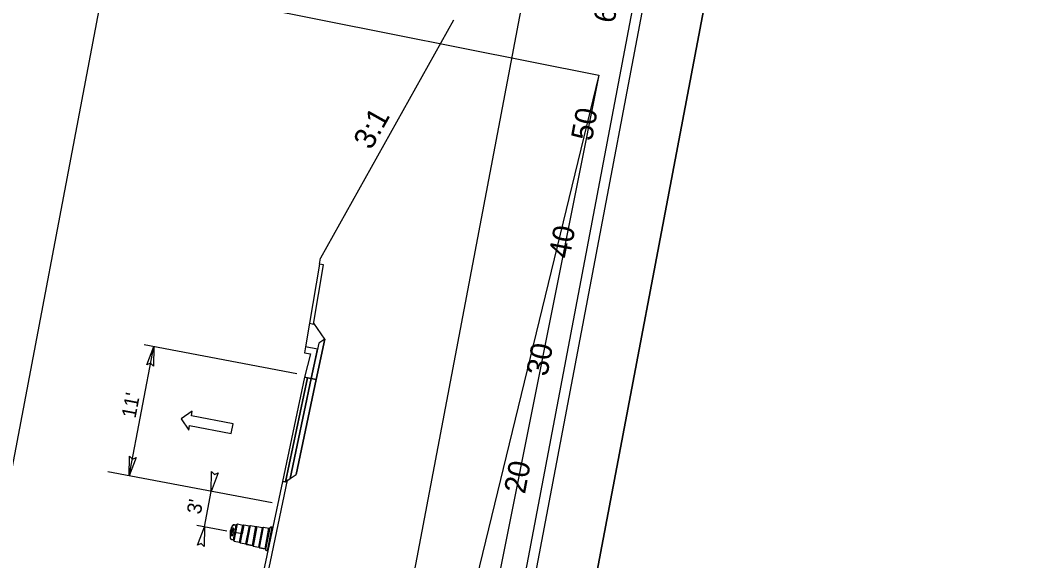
# Model space of a CAD drawing. Extents: x 1615680 to 1617075, y 898420 to 901168.
# Drawn here: x 1616656.3 to 1617075.3, y 900030.6 to 900256.5 of the extents above; entities that cross this region are included whole.
import ezdxf

# ---------------------------------------------------------------- set-up
doc = ezdxf.new("R2010")
doc.units = 0
for name, color, linetype in [('Default', 7, 'Continuous'), ('DEV BORDER CELL', 7, 'Continuous'), ('DEV DRUM SECTIONAL VIEW CELL', 7, 'Continuous'), ('North Arrow', 7, 'Continuous'), ('Old_Level_11', 7, 'Continuous'), ('Prop CMT Pvmt Course 1', 7, 'Continuous'), ('Prop CMT Pvmt Course 2', 7, 'Continuous'), ('Prop CMT Pvmt Course 3', 7, 'Continuous'), ('Prop CMT Subgrade Earthwork', 7, 'Continuous'), ('Prop Conc 4in Sidewalk', 7, 'Continuous'), ('Prop Conc Curb and Gutter', 7, 'Continuous'), ('Prop Corridor Mesh Bottom', 7, 'Continuous'), ('Prop Dimension Text', 7, 'Continuous'), ('Prop XS Finish Grade', 7, 'Continuous'), ('Prop XS Label Text', 7, 'Continuous'), ('Prop XS Offset Labels', 7, 'Continuous'), ('Scratch_Level_0', 7, 'Continuous'), ('Scratch_Level_9', 7, 'Continuous'), ('Sheet Clip Boundary CELL', 7, 'Continuous'), ('Sheet Cross Section CELL', 7, 'Continuous'), ('Sheet Plot Border Outside CELL', 7, 'Continuous')]:
    doc.layers.add(name, color=color, linetype=linetype)

msp = doc.modelspace()

# ---------------------------------------------------------------- linework, layer by layer
at = {"layer": 'Default'}
for points in [[(1616709.31, 900112.48), (1616712.19, 900120.18), (1616712.09, 900111.91), (1616710.87, 900113.19)], [(1616704.81, 900073.84), (1616701.93, 900066.14), (1616702.04, 900074.41), (1616703.26, 900073.13)], [(1616739.07, 900067.34), (1616736.19, 900059.64), (1616736.29, 900067.91), (1616737.51, 900066.62)], [(1616730.51, 900037.2), (1616733.39, 900044.9), (1616733.28, 900036.63), (1616732.06, 900037.92)]]:
    msp.add_lwpolyline(points, close=True, dxfattribs=at)
at = {"layer": 'DEV BORDER CELL'}
msp.add_lwpolyline([(1616014.55, 901139.21), (1615734.74, 899665.53), (1616766.32, 899469.67), (1617046.12, 900943.35)], close=True, dxfattribs=at)
at = {"layer": 'DEV DRUM SECTIONAL VIEW CELL'}
for p, q in [((1616745.47, 900039.42), (1616746.64, 900045.57)), ((1616745.76, 900038.82), (1616747.13, 900046.02)), ((1616746.64, 900045.57), (1616745.92, 900045.71)), ((1616747.13, 900046.02), (1616749.44, 900045.58)), ((1616748.07, 900038.38), (1616749.44, 900045.58)), ((1616748.42, 900038.14), (1616749.85, 900045.69)), ((1616749.44, 900045.58), (1616749.85, 900045.69)), ((1616749.85, 900045.69), (1616752.16, 900045.25)), ((1616750.73, 900037.7), (1616752.16, 900045.25)), ((1616751.08, 900037.45), (1616752.58, 900045.35)), ((1616752.16, 900045.25), (1616752.58, 900045.35)), ((1616752.58, 900045.35), (1616754.89, 900044.91)), ((1616744.82, 900041.14), (1616744.78, 900041.14)), ((1616745.4, 900044.21), (1616745.37, 900044.22)), ((1616753.39, 900037.01), (1616754.89, 900044.91)), ((1616753.74, 900036.76), (1616755.31, 900045.01)), ((1616754.89, 900044.91), (1616755.31, 900045.01)), ((1616755.31, 900045.01), (1616757.62, 900044.57)), ((1616756.05, 900036.33), (1616757.62, 900044.57)), ((1616756.4, 900036.08), (1616758.03, 900044.67)), ((1616757.62, 900044.57), (1616758.03, 900044.67)), ((1616758.03, 900044.67), (1616760.34, 900044.24)), ((1616758.71, 900035.64), (1616760.34, 900044.24)), ((1616759.05, 900035.34), (1616760.77, 900044.39)), ((1616759.75, 900034.81), (1616761.61, 900044.63)), ((1616760.34, 900044.24), (1616760.76, 900044.34)), ((1616761.61, 900044.63), (1616761.23, 900044.7)), ((1616745.47, 900039.42), (1616744.75, 900039.55)), ((1616745.76, 900038.82), (1616748.07, 900038.38)), ((1616748.07, 900038.38), (1616748.42, 900038.14)), ((1616748.42, 900038.14), (1616750.73, 900037.7)), ((1616750.73, 900037.7), (1616751.08, 900037.45)), ((1616751.08, 900037.45), (1616753.39, 900037.01)), ((1616753.39, 900037.01), (1616753.74, 900036.76)), ((1616753.74, 900036.76), (1616756.05, 900036.33)), ((1616756.05, 900036.33), (1616756.4, 900036.08)), ((1616756.4, 900036.08), (1616758.71, 900035.64)), ((1616758.71, 900035.64), (1616759.06, 900035.39)), ((1616759.75, 900034.81), (1616759.37, 900034.88))]:
    msp.add_line(p, q, dxfattribs=at)
for points in [[(1616749.85, 900045.69), (1616749.14, 900041.91), (1616745.29, 900042.64), (1616745.35, 900042.96), (1616745.41, 900043.18), (1616745.46, 900043.38), (1616745.51, 900043.54), (1616745.56, 900043.71), (1616745.61, 900043.86), (1616745.63, 900043.93), (1616745.63, 900043.99), (1616745.6, 900044.07), (1616745.55, 900044.13), (1616745.5, 900044.18), (1616745.44, 900044.21), (1616745.37, 900044.22), (1616745.28, 900044.23), (1616745.2, 900044.2), (1616745.15, 900044.17), (1616745.11, 900044.12), (1616745.08, 900044.09), (1616745.06, 900044.04), (1616745.02, 900043.92), (1616744.98, 900043.79), (1616744.94, 900043.66), (1616744.89, 900043.53), (1616744.85, 900043.36), (1616744.8, 900043.17), (1616744.77, 900043.03), (1616744.74, 900042.9), (1616744.71, 900042.75), (1616744.23, 900042.84), (1616744.27, 900043.07), (1616744.31, 900043.24), (1616744.37, 900043.49), (1616744.42, 900043.65), (1616744.47, 900043.84), (1616744.54, 900044.04), (1616744.63, 900044.28), (1616744.72, 900044.52), (1616744.83, 900044.79), (1616744.94, 900045.02), (1616745.03, 900045.22), (1616745.08, 900045.3), (1616745.13, 900045.39), (1616745.2, 900045.47), (1616745.27, 900045.55), (1616745.35, 900045.59), (1616745.44, 900045.65), (1616745.53, 900045.68), (1616745.63, 900045.71), (1616745.71, 900045.72), (1616745.81, 900045.73), (1616745.89, 900045.72), (1616745.92, 900045.71), (1616746.64, 900045.57), (1616746.74, 900045.7), (1616746.79, 900045.77), (1616746.86, 900045.83), (1616746.93, 900045.9), (1616747.03, 900045.97), (1616747.09, 900046), (1616747.13, 900046.02), (1616749.44, 900045.58)], [(1616750.73, 900037.7), (1616752.16, 900045.25), (1616752.58, 900045.35), (1616754.89, 900044.91), (1616755.31, 900045.01), (1616753.74, 900036.76), (1616753.39, 900037.01), (1616751.08, 900037.45)], [(1616748.42, 900038.14), (1616749.14, 900041.91), (1616745.29, 900042.64), (1616745.25, 900042.45), (1616745.23, 900042.31), (1616745.21, 900042.16), (1616745.19, 900042.01), (1616745.17, 900041.84), (1616745.16, 900041.66), (1616745.15, 900041.47), (1616745.14, 900041.35), (1616745.12, 900041.28), (1616745.08, 900041.23), (1616745.02, 900041.18), (1616744.97, 900041.15), (1616744.91, 900041.13), (1616744.86, 900041.13), (1616744.75, 900041.15), (1616744.7, 900041.18), (1616744.64, 900041.22), (1616744.6, 900041.28), (1616744.57, 900041.36), (1616744.56, 900041.42), (1616744.57, 900041.56), (1616744.58, 900041.76), (1616744.62, 900042.15), (1616744.66, 900042.43), (1616744.69, 900042.64), (1616744.71, 900042.75), (1616744.23, 900042.84), (1616744.19, 900042.64), (1616744.15, 900042.38), (1616744.12, 900042.11), (1616744.09, 900041.83), (1616744.08, 900041.56), (1616744.07, 900041.26), (1616744.07, 900040.91), (1616744.08, 900040.71), (1616744.11, 900040.38), (1616744.12, 900040.24), (1616744.14, 900040.15), (1616744.17, 900040.05), (1616744.21, 900039.95), (1616744.29, 900039.83), (1616744.37, 900039.75), (1616744.44, 900039.69), (1616744.53, 900039.63), (1616744.63, 900039.59), (1616744.75, 900039.55), (1616745.47, 900039.42), (1616745.49, 900039.34), (1616745.51, 900039.26), (1616745.55, 900039.16), (1616745.61, 900039.05), (1616745.66, 900038.96), (1616745.76, 900038.82), (1616748.07, 900038.38)], [(1616756.05, 900036.33), (1616757.62, 900044.57), (1616758.03, 900044.67), (1616760.34, 900044.24), (1616760.76, 900044.34), (1616760.78, 900044.43), (1616760.81, 900044.49), (1616760.85, 900044.56), (1616760.9, 900044.62), (1616760.95, 900044.65), (1616761.01, 900044.68), (1616761.09, 900044.7), (1616761.14, 900044.71), (1616761.19, 900044.71), (1616761.23, 900044.7), (1616761.61, 900044.63), (1616759.75, 900034.81), (1616759.37, 900034.88), (1616759.31, 900034.9), (1616759.25, 900034.92), (1616759.2, 900034.96), (1616759.16, 900035), (1616759.13, 900035.03), (1616759.09, 900035.1), (1616759.06, 900035.16), (1616759.05, 900035.24), (1616759.05, 900035.28), (1616759.05, 900035.34), (1616759.06, 900035.39), (1616758.71, 900035.64), (1616756.4, 900036.08)]]:
    msp.add_lwpolyline(points, close=True, dxfattribs=at)
for centre, radius, start, end in [((1616752.92, 900041.19), 8.85, 152.3001, 186.1986), ((1616745.78, 900044.94), 0.783, 79.2494, 152.3001), ((1616747.78, 900044.84), 1.35, 118.7358, 146.9434), ((1616753.4, 900041.1), 8.85, 160.5754, 177.9234), ((1616744.84, 900041.41), 0.274, 177.9234, 259.2494), ((1616744.87, 900041.41), 0.274, 259.2494, 357.3981), ((1616745.32, 900043.95), 0.274, 79.2494, 160.5754), ((1616753.98, 900040.99), 8.85, 161.1006, 177.3981), ((1616745.35, 900043.95), 0.274, 341.1006, 79.2494), ((1616761.16, 900044.31), 0.392, 79.2494, 169.2494), ((1616744.9, 900040.32), 0.783, 186.1986, 259.2494), ((1616746.8, 900039.69), 1.35, 191.5554, 219.7629), ((1616759.44, 900035.27), 0.392, 169.2494, 259.2494)]:
    msp.add_arc(centre, radius, start, end, dxfattribs=at)
at = {"layer": 'North Arrow'}
msp.add_line((1616761.71, 900054.79), (1616693, 900067.84), dxfattribs=at)
at = {"layer": 'Old_Level_11'}
for p, q in [((1616708.25, 900120.92), (1616772.02, 900108.82)), ((1616701.93, 900066.14), (1616712.19, 900120.18)), ((1616733.39, 900044.9), (1616736.19, 900059.64)), ((1616730.22, 900045.5), (1616742.71, 900043.13))]:
    msp.add_line(p, q, dxfattribs=at)
at = {"layer": 'Prop CMT Pvmt Course 1'}
for p, q in [((1616765.99, 900063.81), (1616749.65, 899986.23)), ((1616767.12, 900063.6), (1616765.99, 900063.81)), ((1616765.99, 900063.81), (1616765.99, 900063.81))]:
    msp.add_line(p, q, dxfattribs=at)
msp.add_lwpolyline([(1616765.99, 900063.81), (1616765.99, 900063.81), (1616765.99, 900063.81), (1616767.22, 900063.58), (1616767.22, 900063.58), (1616776.39, 900107.11), (1616775.17, 900107.35), (1616775.17, 900107.35), (1616765.99, 900063.81)], dxfattribs=at)
at = {"layer": 'Prop CMT Pvmt Course 2'}
msp.add_lwpolyline([(1616767.24, 900063.68), (1616767.24, 900063.68), (1616767.24, 900063.68), (1616769.23, 900065.04), (1616769.23, 900065.04), (1616778.03, 900106.8), (1616776.39, 900107.11), (1616776.39, 900107.11), (1616767.24, 900063.68)], dxfattribs=at)
at = {"layer": 'Prop CMT Pvmt Course 3'}
for p, q in [((1616751.59, 899985.86), (1616768.11, 900064.28)), ((1616768.11, 900064.28), (1616767.12, 900063.6)), ((1616767.12, 900063.6), (1616767.12, 900063.6))]:
    msp.add_line(p, q, dxfattribs=at)
for points in [[(1616778.03, 900106.8), (1616780.08, 900106.41), (1616783.61, 900123.18), (1616781.12, 900121.49), (1616778.03, 900106.8)], [(1616769.23, 900065.04), (1616769.23, 900065.04), (1616769.23, 900065.04), (1616771.72, 900066.73), (1616771.72, 900066.73), (1616780.08, 900106.41), (1616778.03, 900106.8), (1616778.03, 900106.8), (1616769.23, 900065.04)]]:
    msp.add_lwpolyline(points, dxfattribs=at)
at = {"layer": 'Prop CMT Subgrade Earthwork'}
for points in [[(1616783.61, 900123.18), (1616779.01, 900129.94)], [(1616783.61, 900123.18), (1616780.08, 900106.41), (1616780.08, 900106.41)], [(1616780.08, 900106.41), (1616771.72, 900066.73), (1616771.72, 900066.73)]]:
    msp.add_lwpolyline(points, dxfattribs=at)
at = {"layer": 'Prop Conc 4in Sidewalk'}
msp.add_lwpolyline([(1616777.3, 900129.85), (1616778.93, 900129.49), (1616783.12, 900154.24), (1616781.47, 900154.5), (1616777.3, 900129.85)], dxfattribs=at)
at = {"layer": 'Prop Conc Curb and Gutter'}
msp.add_lwpolyline([(1616775.17, 900107.35), (1616775.17, 900107.35), (1616775.17, 900107.35), (1616778.03, 900106.8), (1616778.03, 900106.8), (1616780.61, 900119.04), (1616775.63, 900119.99), (1616775.63, 900119.99), (1616775.17, 900117.53), (1616775.17, 900117.53), (1616775.17, 900117.53), (1616777.62, 900117.06), (1616775.17, 900107.35)], dxfattribs=at)
at = {"layer": 'Prop Corridor Mesh Bottom'}
msp.add_lwpolyline([(1616775.17, 900107.35), (1616776.39, 900107.11)], dxfattribs=at)
at = {"layer": 'Prop Dimension Text'}
for p, q in [((1616728.29, 900093.08), (1616723.64, 900089.97)), ((1616727.94, 900091.22), (1616728.29, 900093.08)), ((1616723.64, 900089.97), (1616726.8, 900085.25)), ((1616745.34, 900087.91), (1616727.94, 900091.22)), ((1616744.56, 900083.81), (1616745.34, 900087.91)), ((1616726.8, 900085.25), (1616727.16, 900087.11)), ((1616727.16, 900087.11), (1616744.56, 900083.81))]:
    msp.add_line(p, q, dxfattribs=at)
at = {"layer": 'Prop XS Finish Grade'}
for points in [[(1616837.46, 900256.47), (1616781.89, 900156.97), (1616781.89, 900156.97)], [(1616781.47, 900154.5), (1616781.89, 900156.97)], [(1616777.3, 900129.85), (1616777.3, 900129.85), (1616775.63, 900119.99)]]:
    msp.add_lwpolyline(points, dxfattribs=at)
at = {"layer": 'Scratch_Level_0'}
msp.add_lwpolyline([(1616054.34, 901080.76), (1615793.19, 899705.33), (1616726.52, 899528.12), (1616890.46, 900391.55), (1616774.26, 900413.61), (1616871.48, 900925.61)], close=True, dxfattribs=at)
at = {"layer": 'Sheet Clip Boundary CELL'}
for points in [[(1616176.29, 901060.7), (1616848.46, 900914.27), (1616896.28, 900812.91), (1616872.94, 900688.21), (1616835.87, 900695.21), (1616753.94, 900262.18), (1616898.09, 900233.43), (1616734.79, 899562.1), (1616202.98, 899609.43), (1616198.71, 899647.14), (1615822.69, 899825.07), (1616054.34, 901080.76)], [(1616176.29, 901060.7), (1616914, 900899.99), (1616896.28, 900812.91), (1616872.94, 900688.21), (1616835.87, 900695.21), (1616753.94, 900262.18), (1616898.09, 900233.43), (1616747.89, 899480.25), (1615915.8, 899646.19), (1615751.76, 899738.03), (1615981.58, 900932.46), (1616145.94, 900899.57)]]:
    msp.add_lwpolyline(points, close=True, dxfattribs=at)
at = {"layer": 'Sheet Cross Section CELL'}
for p, q in [((1616723.15, 900439.56), (1616559.31, 899576.61)), ((1616774.52, 899535.75), (1616938.37, 900398.7))]:
    msp.add_line(p, q, dxfattribs=at)
at = {"layer": 'Sheet Plot Border Outside CELL'}
for points in [[(1616760.47, 899304.87), (1615679.78, 899510.06), (1615994.65, 901168.43), (1617075.34, 900963.24)], [(1616760.47, 899304.87), (1617075.34, 900963.24), (1615994.65, 901168.43), (1615679.78, 899510.06)]]:
    msp.add_lwpolyline(points, close=True, dxfattribs=at)

# ---------------------------------------------------------------- texts
at = {"layer": 'Default'}
for s, p in [("11'", (1616704.55, 900089.92)), ("3'", (1616731.79, 900049.8))]:
    msp.add_text(s, height=6, rotation=79.2493, dxfattribs=at).set_placement(p)
at = {"layer": 'Prop XS Label Text'}
msp.add_text('3:1', height=9, rotation=60.8161, dxfattribs=at).set_placement((1616802.96, 900201.87))
at = {"layer": 'Prop XS Offset Labels'}
for s, p in [('60', (1616904.57, 900254.78)), ('50', (1616895.24, 900205.66)), ('40', (1616885.91, 900156.54)), ('30', (1616876.59, 900107.42)), ('20', (1616867.26, 900058.29))]:
    msp.add_text(s, height=9, rotation=79.2494, dxfattribs=at).set_placement(p)
at = {"layer": 'Scratch_Level_9'}
for p in [(1616781.47, 900154.5), (1616777.3, 900129.85), (1616777.62, 900117.06), (1616775.17, 900107.34), (1616775.17, 900107.34)]:
    msp.add_text('X', height=0.00125, rotation=79.2494, dxfattribs=at).set_placement(p)

doc.saveas('drawing.dxf')
